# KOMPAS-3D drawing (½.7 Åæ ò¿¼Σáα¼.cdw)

Views: Вид 1, Вид 2
Referenced files in C:\Program Files\ASCON\KOMPAS-3D V10\Sys\: SPDS.lcs, Graphic.lcs
Referenced files in \\F-server\проектирование\Проекты\РЗА и ПА Тюменские РС\4. Проект\ЭП\Туринская\Рабочая документация\: план располодения оборудования на ПС.cdw
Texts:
  Текст на чертеже
  Размерные надписи
  Шероховатость
  Линия-выноска #1
  Линия-выноска #2
  Линия-выноска #3
  Отклонения формы и база
  Заголовок таблицы
  Ячейка таблицы
  Стрелка вида
  Обозначение изменения
  Фигурная скобка
  Номер узла
  Марка координационной оси
  VRCB
  Выносная надпись
  Обозначение узла
  Марка/позиционное обозначение с линией-выноской
  Марка/позиционное обозначение на линии
  Марка/позиционное обозначение без линии-выноски
  Лит-Масса-Масштаб
  Материал-Предприятие
  Title Specification
  Body Specification ( left align )
  Body Specificaton ( centered )
  Без имени
  Normal
  heading 1
  Знак Знак Знак Знак Знак Знак
  Verdana
  Body Text
  MS Sans Serif
  Txt
  Simplex
  TXT
  Обычный
  Термин
  Список определений
  Адрес
  Цитаты
  Форматированный
  Courier New
  Z-конец формы
  Z-начало формы
  Additional DXF text style 0
  Абзац Знак
  Body Text 3
  Title
  ТекстШаг1
  Шрифт 2.5
  Заголовки
  txt
  heading 2
  AGOpus
  footer
  Денис
  RUSTXT
  Обычный (веб)
  ООббыыччнныыйй
  Definition Term
  Definition List
  Address
  Blockquote
  Preformatted
  z-Bottom of Form
  z-Top of Form
  header
  NormalParagraphStyle
  ссылки
  Подпись в квадратике
  табл
  цепи
  Маркировка
  клеммы, контакты
  тексты табл
  Тексты. 3,2
  ЗОНА_привяз
  текст переноса
  ТТееррммиинн
  ССппииссоокк ооппррееддееллеенниийй
  ААддрреесс
  ЦЦииттааттыы
  ФФооррммааттиирроовваанннныыйй
  Z-ккооннеецц ффооррммыы
  Z-ннааччааллоо ффооррммыы
  GOST 2.304 type A
  rustxt
  heading 8
  heading 3
  heading 6
  heading 7
  russ
  heading 4
  heading 5
  heading 9
  HeliosLight
  Pa3
  Pa1
  Три с половиной
  style2
  Table Contents
  Table Heading
  ГОСТ_МНЕ
  ESK - Обозначение
  маркировка
  ISOCP
  ROMANS
  SIMPLEX
  Текст 3,5
  Tahoma
  CNBNDG+TimesNewRoman
  Subtitle
  FR5
  romanc
  eskd1
  Pa15
  Pa18
  Аппараты
  подписи
  Состав чартежа
  ячейка табл.
  Ссылки
  Пояснения
  Клеммник текст
  CM12
  romans
  gif
  Пояснения 2
  текст табл
  ISOCPEUR
  CC С?т?и?л?ь? П?о? ц?е?н?т?р?у?
  Normal (Web)
  ошиновка
  лотки
  съемка
  Демонтаж
  Монтаж
  Молниеотвод
  Экспликация зданий и сооружений
  Номер
  на плане
  Постоянные здания и сооружения
  ОПУ 8 №1
  Существующее
  ОПУ 8 №2
  КРУН 10 кВ
  Трансформатор 1Т, маслоприемник
  Существующий
  Трансформатор 2Т, маслоприемник
  Временные здания и сооружения
  III
  Вагон-дом для кратковременного отдых рабочих
  Уборная
  Дизельная электростанция
  Контейнеры для ТБО (0,75м 3 ) и жидких хоз.-быт.стоков(1м 3 )
  «Екатерина» 9,0х3,0
  Туалетная кабина "Люкс"
  ОАО ПКТИпромстрой
  АДС 45-Т400 РЯ
  Примечания:
  1. Для нужд строительства (размещение задействованного в строительстве персонала, обеспечение
  электроэнергией) использовать временные мобильные инвентарные здания;
  2. При выполнении всех строительно-монтажных работ на площадке необходимо руководствоваться
  требованиями СНиП 12-03-2001 "Безопасность труда в строительстве. Общие требования",
  СНиП 12-04-2002 "Безопасность труда в строительстве. Строительное производство", а также
  ПОТ-РМ-016-2001/РД 153-34.0-03.150-00 "Межотраслевые правила по охране труда (правила
  безопасности) при эксплуатации электроустановок";
  3. Наружное освещение строительной площадки осуществляется за счет существующего освещения;
  4. Под временные сооружения (поз. II, III и IV) устраивается площадка из дорожных плит ПД 60-20 на
  щебеночном основании толщиной 15см;
  5. На период строительства для электроснабжения временных зданий и сооружений использовать ди-
  зельную электростанцию. Прокладку  кабеля от дизельной электростанции до вагончиков выполнить
  в воздушном исполнении в гофрированной трубе диаметром 30 мм, на вагончиках кабель закрепить
  скобами. Щиток временного электроснабжения навесить на стенку вагона-дома для отдыха рабочих;
  6. При выполнении монтажных работ использовать инвентарные лестницы и леса;
  7. На паспорте-стенде строительного объекта  должен быть план пожарной защиты с нанесенными
  строящимися и вспомогательными зданиями и сооружениями, въездами, подъездами, местонахождениями
  водоисточников, средств пожаротушения и связи (согласно ППБ-01-03 п.575);
  8. Тонкой линией изображено существующее оборудование, замена которого проектом не предусматривается,
  утолщенной - демонтируемое оборудование.
  - предупреждающий знак
  "Опасно. Возможно падение груза"
  "Опасность поражения электрическим током"
  - стоянка крана во время производства работ
  - стенд с противопожарным
  инвентарем
  - знак ограничения поворота стрелы
  - опасная зона работы при перемещении грузов
  - пути перемещения строительной техники
  Условные обозначения:
  - паспорт-стенд строительного
  объекта
  - запрещающий знак ограничения
  скорости движения автомобиля
  в.заг.40,98
  в.заг.40,85
  шк.
  в.кр.п.38,95
  в.заг.40,81
  в.заг.40,96
  в.кр.п.38,94
  ср.п.49,43
  каб.лот.
  каб.лоток
  ОПУ 2
  в.зд.38,44
  в.зд.38,15
  КРУН-10 кВ
  ОПУ 1
  в.зд.38,46
  ж/б пл.
  каб.эстакада 10 кВ
  об-35,00
  об-34,60
  РП 2
  РП 1
  кабели 10 кВ по забору
  КМУ ИНМАН ИМ-150
  Слой 1
  ВЛ 110 кВ
  K5LT_BASIC_RGB_0_0_255_THICK_0.6
  K5LT_AXLED_RGB_255_128_0_SC_1_THICK_0.09
  K5LT_DASHED_RGB_0_0_0_SC_1_THICK_0.09
  K5LT_AXLED_RGB_255_128_0_SC_1_THICK_0.18
  POLYLINE_STYLE_0.18_RGB_0_0_0
  POLYLINE_STYLE_0.20_RGB_0_0_0
  POLYLINE_STYLE_0.18_RGB_0_80_80
  Стили документа
  Бортовой автомобиль КамАЗ 43114-027-02
  АТ ППР#010#0104
  ГИП
  Н.контр.
  Гл.спец.
  Разраб.
  Перезавод ВЛ на ПС Тюмень. Реконструкция устройств
  РЗ и ПА на обратных концах отходящих ВЛ,
  ВОЛС Тюменского ТПО
  ПС 110/10 кВ Химфарм
  Матвеев
  Ромин
  Шашерин
  Строительный генеральный план
  Королева
  Микрюков
  Общие технические условия на средний ремонт
Dimensions and other numbers on the sheet: 16/01-ПОД; 7; 2,5; 1,8; 2.5; 3,2_; 3.5; 3,2; 2,5 (контакты, клеммы); 3,2 (надписи); 3,2 (Зоны); 5; 2,5_01; 2,5_3; 3,5_01; 3,5_tabl; 5_заголовок; 2,3_; 3,2_зона не привяз; 3,5; 3.2 маркировка; 3,2 элементы; 3,2 линия; 3,2 таблица; 2,5 грязносинь; 2.5 курсив; 2.5_Э5_надписи; 2.5_Э5_ссылки; 2.5_кабель; 3.2; 2.5 надписи; 3 и 5; 5,0_белый_подчёркнутый; 3.2 фиол; 3.2 (текст); 1; 2; 3; 4; 9,6; 34,78; 34,40; 34,47; 34,37; 34,52; 34,80; 34,65; 35,01; 34,73; 34,62; 34,60; 34,49; 34,56; 34,93; 34,88; 34,81; 34,76; 34,79; 34,74; 34,32; 34,66; 35,83; 34,38; 35,92; 34,42; 35,37; 35,15; 35,32; 34,77; 34,58; 34,46; 34,59; 35,00; 34,83; 34,87; 34,53; 34,28; 34,68; 34,67; 34,48; 34,82; 35,07; 34,54; 3 пр.; 7 пр.; 110 кВ; 1065; 1780; 1800; 1500; 16; 20; 19; 18; 17; 05.13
